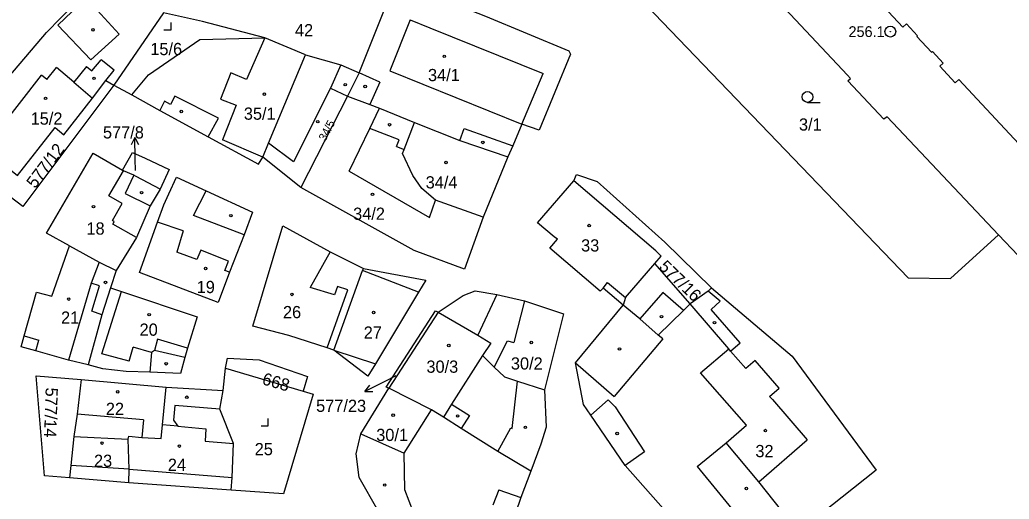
# Model space of a CAD drawing. Extents: x -758582 to -751794, y -998770 to -994350.
# Drawn here: x -754634.2 to -754496.6, y -996827 to -996760.3 of the extents above; entities that cross this region are included whole.
import ezdxf

# ---------------------------------------------------------------- set-up
doc = ezdxf.new("R2010")
doc.units = 0
for name, color, linetype in [('Hranice parcel', 7, 'Continuous'), ('Parcelní čísla', 7, 'Continuous'), ('Pop  PČ popisy', 7, 'Continuous'), ('Vnitřní kresba', 7, 'Continuous'), ('Značky bodu BP', 7, 'Continuous'), ('Značky budov', 7, 'Continuous'), ('Značky kultur', 7, 'Continuous')]:
    doc.layers.add(name, color=color, linetype=linetype)

msp = doc.modelspace()

# ---------------------------------------------------------------- linework, layer by layer
at = {"layer": 'Hranice parcel'}
for p, q in [((-754586.97, -996767.66), (-754583, -996757.68)), ((-754630.49, -996762.03), (-754626.47, -996757.97)), ((-754614.18, -996759.28), (-754621.09, -996769.34)), ((-754642.14, -996775.76), (-754630.49, -996762.03)), ((-754594.45, -996765.16), (-754600.1, -996762.77)), ((-754586.97, -996767.66), (-754588.61, -996770.89)), ((-754621.09, -996769.34), (-754618.62, -996770.71)), ((-754618.62, -996770.71), (-754614.71, -996772.89)), ((-754588.61, -996770.89), (-754595.09, -996783.62)), ((-754595.09, -996783.62), (-754600.38, -996779.37)), ((-754566.31, -996779.33), (-754569.76, -996787.73)), ((-754495.35, -996793.06), (-754498.09, -996790.19)), ((-754620.77, -996795.17), (-754621.55, -996797.57)), ((-754576.01, -996800.97), (-754582.85, -996811.54)), ((-754605.91, -996811.83), (-754605.57, -996808.76)), ((-754605.57, -996808.76), (-754594.79, -996811.96)), ((-754625.65, -996810.32), (-754613.81, -996811.37)), ((-754613.81, -996811.37), (-754605.91, -996811.83)), ((-754594.79, -996811.96), (-754593.39, -996812.37)), ((-754626.65, -996818.24), (-754619.11, -996818.64)), ((-754619.04, -996824.72), (-754627.29, -996824.01)), ((-754604.8, -996825.7), (-754619.04, -996824.72))]:
    msp.add_line(p, q, dxfattribs=at)
for points in [[(-754517.71, -996734.79), (-754521.88, -996738.79), (-754520.85, -996739.93), (-754523.11, -996742.06), (-754524.18, -996740.92), (-754527.46, -996744.01), (-754511.37, -996761.27), (-754510.88, -996760.84), (-754509.34, -996762.49), (-754509.43, -996762.58), (-754507.38, -996764.77), (-754507.28, -996764.69), (-754505.78, -996766.3), (-754506.25, -996766.72), (-754504.11, -996769.04), (-754503.6, -996768.55), (-754490.16, -996782.99), (-754490.7, -996783.49), (-754488.08, -996786.29), (-754495.35, -996793.06)], [(-754498.09, -996790.19), (-754513.58, -996773.76), (-754514.01, -996774.11), (-754519.03, -996768.77), (-754518.65, -996768.41), (-754519.06, -996767.99), (-754542.19, -996743.28)], [(-754550.52, -996754.59), (-754510.63, -996796.17), (-754504.74, -996796.25), (-754498.09, -996790.19)], [(-754576.26, -996757.01), (-754569.4, -996759.74), (-754557.83, -996764.59), (-754557.59, -996765.06), (-754561.98, -996775.61), (-754564.36, -996774.79), (-754565.63, -996777.81), (-754566.31, -996779.33)], [(-754600.1, -996762.77), (-754608.76, -996760.51), (-754614.18, -996759.28)], [(-754618.62, -996770.71), (-754616.29, -996767.9), (-754609.14, -996762.99), (-754600.1, -996762.77)], [(-754600.38, -996779.37), (-754599.61, -996777.41), (-754594.45, -996765.16)], [(-754594.45, -996765.16), (-754589.54, -996766.52), (-754586.97, -996767.66)], [(-754638.51, -996778.73), (-754634.52, -996781.92), (-754629.25, -996775.27), (-754628.08, -996776.26), (-754624.09, -996771.15), (-754622.2, -996768.72), (-754621.09, -996769.34)], [(-754621.09, -996769.34), (-754633.76, -996786.26), (-754640.43, -996781.18), (-754638.51, -996778.73)], [(-754588.61, -996770.89), (-754585.5, -996772.06), (-754584.18, -996772.56), (-754579.3, -996774.56)], [(-754614.71, -996772.89), (-754607.97, -996776.56), (-754601, -996780.37), (-754600.38, -996779.37)], [(-754569.76, -996787.73), (-754576.38, -996785.36), (-754578.28, -996783.73), (-754579.54, -996781.91), (-754580.96, -996778.85), (-754580.74, -996778.31), (-754579.3, -996774.56)], [(-754579.3, -996774.56), (-754572.98, -996777.04), (-754566.31, -996779.33)], [(-754627.28, -996791.74), (-754630.45, -996789.97), (-754623.98, -996778.83), (-754619.92, -996781.17)], [(-754619.92, -996781.17), (-754618.52, -996778.75), (-754616.77, -996779.54), (-754613.42, -996781.11), (-754614.68, -996783.82)], [(-754614.68, -996783.82), (-754618.01, -996782.06), (-754618.31, -996781.9), (-754619.77, -996781.26), (-754619.92, -996781.17)], [(-754617.55, -996795.43), (-754615.04, -996788.43), (-754614.17, -996786), (-754613.46, -996784.47), (-754612.4, -996782.17), (-754608.29, -996784.05), (-754601.81, -996787.05), (-754602.99, -996790.2), (-754605.02, -996795.38), (-754606.62, -996799.61), (-754617.55, -996795.43)], [(-754550.29, -996799.98), (-754553.08, -996797.59), (-754553.47, -996798.05), (-754560.48, -996792.05), (-754559.41, -996790.8), (-754559.89, -996790.48), (-754562.17, -996788.53), (-754557.12, -996782.67)], [(-754557.12, -996782.67), (-754556.79, -996781.79), (-754553.88, -996782.77), (-754544.49, -996791.21), (-754537.99, -996797.55)], [(-754540.94, -996799.81), (-754545.86, -996794.18), (-754544.98, -996793.17), (-754545.72, -996792.4), (-754557.12, -996782.67)], [(-754614.68, -996783.82), (-754616.04, -996786.16), (-754617.97, -996790.55), (-754620.77, -996795.17)], [(-754569.76, -996787.73), (-754572.33, -996794.98), (-754579.34, -996792.35), (-754595.09, -996783.62)], [(-754590.53, -996806.24), (-754591.46, -996805.92), (-754596.78, -996804.2), (-754601.77, -996802.92), (-754597.6, -996788.95), (-754591.03, -996792.57), (-754586.41, -996794.87)], [(-754624.7, -996808.3), (-754627.42, -996807.61), (-754631.95, -996806.33), (-754634, -996805.77), (-754633.58, -996804.24), (-754631.86, -996798.17), (-754629.75, -996798.74), (-754627.28, -996791.74)], [(-754627.28, -996791.74), (-754623.15, -996793.98), (-754620.77, -996795.17)], [(-754586.41, -996794.87), (-754577.73, -996796.52), (-754578.74, -996798.19), (-754584.74, -996808.14), (-754585.77, -996809.85), (-754590.53, -996806.24)], [(-754590.53, -996806.24), (-754586.53, -996795.15), (-754586.41, -996794.87)], [(-754621.55, -996797.57), (-754620.04, -996798.07), (-754609.54, -996801.58), (-754610.86, -996805.95), (-754611.22, -996807.27), (-754611.84, -996809.48), (-754616.11, -996809.31), (-754619.38, -996809.21), (-754622.65, -996808.83), (-754624.7, -996808.3)], [(-754621.55, -996797.57), (-754622.76, -996801.3), (-754624.7, -996808.3)], [(-754537.99, -996797.55), (-754538.47, -996798.02), (-754540.94, -996799.81)], [(-754537.99, -996797.55), (-754526.76, -996807.06), (-754515.08, -996822.93), (-754525.88, -996831.52)], [(-754576.01, -996800.97), (-754572.55, -996798.64), (-754570.84, -996797.96), (-754567.83, -996798.5)], [(-754567.83, -996798.5), (-754570.47, -996804.13), (-754568.7, -996805.26), (-754569.84, -996806.98), (-754568.21, -996808.6), (-754566.8, -996809.97), (-754564.95, -996810.55), (-754561.2, -996811.74)], [(-754567.83, -996798.5), (-754564.02, -996799.39), (-754558.56, -996801.18), (-754561.2, -996811.74)], [(-754525.88, -996831.52), (-754529.97, -996834.72), (-754530.8, -996833.6), (-754535.24, -996836.36), (-754537.32, -996836.16), (-754539.06, -996834.69), (-754550.01, -996822.3), (-754554.77, -996815.29), (-754555.79, -996813.82), (-754556.89, -996808.01), (-754550.29, -996799.98)], [(-754540.94, -996799.81), (-754541.88, -996800.73), (-754545.4, -996804.17), (-754547.97, -996801.87), (-754550.29, -996799.98)], [(-754525.88, -996831.52), (-754531.43, -996824.54), (-754535.95, -996819.14), (-754533.11, -996816.66), (-754539.52, -996809.39), (-754535.59, -996806.07), (-754540.94, -996799.81)], [(-754582.85, -996811.54), (-754583.23, -996811.38), (-754576.38, -996800.76), (-754576.01, -996800.97)], [(-754605.57, -996808.76), (-754605.32, -996807.35), (-754600.92, -996807.59), (-754594.19, -996809.9), (-754594.79, -996811.96)], [(-754627.29, -996824.01), (-754630.74, -996823.71), (-754631.93, -996809.82), (-754625.65, -996810.32)], [(-754625.65, -996810.32), (-754626.22, -996815.14), (-754626.65, -996818.24)], [(-754619.11, -996818.64), (-754619.03, -996818.22), (-754617.21, -996818.41), (-754614.52, -996818.55), (-754614.33, -996816.61), (-754613.81, -996811.37)], [(-754563.13, -996823.1), (-754564.53, -996826.74), (-754565.27, -996828.9), (-754569.1, -996839.07), (-754577.26, -996836.37), (-754579.33, -996834.34), (-754581.37, -996832.02), (-754584.33, -996828.61), (-754587, -996823.94), (-754587.4, -996820.67), (-754586.75, -996817.88), (-754582.85, -996811.54)], [(-754563.13, -996823.1), (-754567.7, -996820.33), (-754572.79, -996817.13), (-754575.28, -996815.57), (-754576.94, -996814.54), (-754582.85, -996811.54)], [(-754604.8, -996825.7), (-754604.63, -996823.94), (-754604.49, -996819.21), (-754606.35, -996814.45), (-754605.91, -996811.83)], [(-754593.39, -996812.37), (-754597.52, -996826.21), (-754604.8, -996825.7)], [(-754561.2, -996811.74), (-754560.98, -996816.97), (-754561.71, -996819.34), (-754563.13, -996823.1)], [(-754626.65, -996818.24), (-754627.08, -996822.31), (-754627.29, -996824.01)], [(-754619.04, -996824.72), (-754618.99, -996822.78), (-754619.11, -996818.64)]]:
    msp.add_lwpolyline(points, dxfattribs=at)
at = {"layer": 'Pop  PČ popisy'}
for p, q in [((-754618.19, -996776.65), (-754618.68, -996777.66)), ((-754618.14, -996779.65), (-754618.19, -996776.65)), ((-754618.19, -996776.65), (-754617.67, -996777.64)), ((-754618.11, -996781.23), (-754618.14, -996779.65)), ((-754581.9, -996809.79), (-754583.52, -996810.64)), ((-754583.52, -996810.64), (-754586.19, -996812)), ((-754586.19, -996812), (-754585.53, -996811.1)), ((-754586.19, -996812), (-754585.07, -996811.99))]:
    msp.add_line(p, q, dxfattribs=at)
at = {"layer": 'Vnitřní kresba'}
for p, q in [((-754624.94, -996757.21), (-754628.9, -996760.99)), ((-754620.36, -996762.25), (-754624.94, -996757.21)), ((-754579.88, -996760.26), (-754582.71, -996767.35)), ((-754579.88, -996760.26), (-754577.15, -996761.36)), ((-754624.3, -996765.83), (-754628.9, -996760.99)), ((-754577.15, -996761.36), (-754561.42, -996767.72)), ((-754624.3, -996765.83), (-754620.36, -996762.25)), ((-754600.1, -996762.77), (-754602.68, -996768.58)), ((-754624.15, -996767.37), (-754622.87, -996765.85)), ((-754621.06, -996767.26), (-754622.87, -996765.85)), ((-754630.43, -996768.56), (-754629.08, -996766.88)), ((-754626.65, -996768.96), (-754629.08, -996766.88)), ((-754624.92, -996766.76), (-754626.65, -996768.96)), ((-754624.92, -996766.76), (-754624.15, -996767.37)), ((-754622.2, -996768.72), (-754621.06, -996767.26)), ((-754589.54, -996766.52), (-754590.96, -996769.76)), ((-754582.71, -996767.35), (-754564.36, -996774.79)), ((-754639.16, -996778.21), (-754631.17, -996767.99)), ((-754630.43, -996768.56), (-754631.17, -996767.99)), ((-754604.83, -996767.64), (-754606.27, -996771.29)), ((-754602.68, -996768.58), (-754604.83, -996767.64)), ((-754584.13, -996768.92), (-754586.97, -996767.66)), ((-754584.13, -996768.92), (-754585.5, -996772.06)), ((-754564.36, -996774.79), (-754561.42, -996767.72)), ((-754626.65, -996768.96), (-754624.09, -996771.15)), ((-754590.96, -996769.76), (-754596.12, -996780.02)), ((-754590.96, -996769.76), (-754588.61, -996770.89)), ((-754614.07, -996771.6), (-754614.71, -996772.89)), ((-754613.21, -996772.03), (-754614.07, -996771.6)), ((-754612.62, -996770.88), (-754613.21, -996772.03)), ((-754606.56, -996773.97), (-754612.62, -996770.88)), ((-754606.27, -996771.29), (-754604.09, -996772.16)), ((-754604.09, -996772.16), (-754606, -996776.99)), ((-754585.53, -996775.41), (-754584.18, -996772.56)), ((-754607.97, -996776.56), (-754606.56, -996773.97)), ((-754588.39, -996781.31), (-754585.53, -996775.41)), ((-754581.41, -996776.96), (-754585.53, -996775.41)), ((-754572.98, -996777.04), (-754572.4, -996775.37)), ((-754572.4, -996775.37), (-754565.63, -996777.81)), ((-754600.38, -996779.37), (-754606, -996776.99)), ((-754581.8, -996777.91), (-754581.41, -996776.96)), ((-754596.12, -996780.02), (-754599.61, -996777.41)), ((-754581.8, -996777.91), (-754580.74, -996778.31)), ((-754621.8, -996784.78), (-754619.77, -996781.26)), ((-754618.31, -996781.9), (-754619.52, -996784.43)), ((-754588.39, -996781.31), (-754577.21, -996787.77)), ((-754610.05, -996787.48), (-754608.29, -996784.05)), ((-754619.96, -996785.83), (-754621.8, -996784.78)), ((-754619.52, -996784.43), (-754616.04, -996786.16)), ((-754577.21, -996787.77), (-754576.38, -996785.36)), ((-754621.3, -996788.2), (-754619.96, -996785.83)), ((-754602.99, -996790.2), (-754610.05, -996787.48)), ((-754621.05, -996788.36), (-754621.3, -996788.2)), ((-754621.25, -996788.7), (-754621.05, -996788.36)), ((-754617.97, -996790.55), (-754621.25, -996788.7)), ((-754611.47, -996789.63), (-754615.04, -996788.43)), ((-754611.47, -996789.63), (-754612.37, -996792.58)), ((-754609.55, -996793.63), (-754612.37, -996792.58)), ((-754609.03, -996792.33), (-754609.55, -996793.63)), ((-754605.15, -996793.85), (-754609.03, -996792.33)), ((-754591.03, -996792.57), (-754593.79, -996797.52)), ((-754623.15, -996793.98), (-754624.27, -996796.93)), ((-754605.65, -996795.14), (-754605.15, -996793.85)), ((-754549.96, -996798.92), (-754545.86, -996794.18)), ((-754605.02, -996795.38), (-754605.65, -996795.14)), ((-754578.74, -996798.19), (-754586.53, -996795.15)), ((-754624.27, -996796.93), (-754627.42, -996807.61)), ((-754623.12, -996797.27), (-754624.27, -996796.93)), ((-754624.18, -996800.81), (-754623.12, -996797.27)), ((-754590.41, -996798.55), (-754593.79, -996797.52)), ((-754590.02, -996797.39), (-754590.41, -996798.55)), ((-754588.58, -996797.86), (-754590.02, -996797.39)), ((-754553.08, -996797.59), (-754552.45, -996796.82)), ((-754552.45, -996796.82), (-754549.96, -996798.92)), ((-754622.8, -996806.73), (-754620.04, -996798.07)), ((-754591.46, -996805.92), (-754588.58, -996797.86)), ((-754549.96, -996798.92), (-754550.29, -996799.98)), ((-754544.76, -996798.2), (-754547.97, -996801.87)), ((-754541.88, -996800.73), (-754544.76, -996798.2)), ((-754536.8, -996799.42), (-754538.47, -996798.02)), ((-754564.02, -996799.39), (-754565.47, -996805.16)), ((-754538.05, -996800.56), (-754536.8, -996799.42)), ((-754534.01, -996805.21), (-754538.05, -996800.56)), ((-754622.76, -996801.3), (-754624.18, -996800.81)), ((-754576.01, -996800.97), (-754570.47, -996804.13)), ((-754633.58, -996804.24), (-754631.54, -996804.85)), ((-754544.74, -996804.67), (-754551.52, -996812.7)), ((-754544.74, -996804.67), (-754545.4, -996804.17)), ((-754631.95, -996806.33), (-754631.54, -996804.85)), ((-754618.97, -996807.76), (-754618.43, -996805.84)), ((-754615.88, -996806.55), (-754618.43, -996805.84)), ((-754615.02, -996804.72), (-754615.44, -996806.3)), ((-754610.86, -996805.95), (-754615.02, -996804.72)), ((-754568.21, -996808.6), (-754566.35, -996804.92)), ((-754566.35, -996804.92), (-754565.47, -996805.16)), ((-754535.33, -996806.37), (-754535.59, -996806.07)), ((-754535.33, -996806.37), (-754534.01, -996805.21)), ((-754618.97, -996807.76), (-754622.8, -996806.73)), ((-754615.88, -996806.55), (-754616.11, -996809.31)), ((-754615.44, -996806.3), (-754615.88, -996806.55)), ((-754611.22, -996807.27), (-754615.44, -996806.3)), ((-754590.53, -996806.24), (-754584.74, -996808.14)), ((-754569.84, -996806.98), (-754574.14, -996813.77)), ((-754533.2, -996808.8), (-754535.33, -996806.37)), ((-754556.89, -996808.01), (-754551.52, -996812.7)), ((-754531.91, -996807.69), (-754533.2, -996808.8)), ((-754528.58, -996811.52), (-754531.91, -996807.69)), ((-754565.7, -996817.16), (-754564.95, -996810.55)), ((-754529.91, -996812.67), (-754528.58, -996811.52)), ((-754529.49, -996813.12), (-754529.91, -996812.67)), ((-754612.61, -996813.94), (-754612.8, -996815.97)), ((-754606.35, -996814.45), (-754612.61, -996813.94)), ((-754574.14, -996813.77), (-754575.28, -996815.57)), ((-754574.14, -996813.77), (-754571.64, -996815.31)), ((-754552.35, -996813.15), (-754554.77, -996815.29)), ((-754551.38, -996814.13), (-754552.35, -996813.15)), ((-754551.38, -996814.13), (-754547.32, -996820.39)), ((-754529.49, -996813.12), (-754524.67, -996818.72)), ((-754616.98, -996815.94), (-754626.22, -996815.14)), ((-754580.71, -996820.56), (-754576.94, -996814.54)), ((-754571.64, -996815.31), (-754572.79, -996817.13)), ((-754616.98, -996815.94), (-754617.21, -996818.41)), ((-754612.22, -996816.81), (-754614.33, -996816.61)), ((-754612.8, -996815.97), (-754612.22, -996816.81)), ((-754612.22, -996816.81), (-754608.33, -996817.18)), ((-754567.7, -996820.33), (-754565.91, -996817.05)), ((-754565.91, -996817.05), (-754565.7, -996817.16)), ((-754608.33, -996817.18), (-754608.43, -996818.89)), ((-754586.75, -996817.88), (-754580.71, -996820.56)), ((-754608.43, -996818.89), (-754604.49, -996819.21)), ((-754540, -996822.41), (-754535.95, -996819.14)), ((-754531.43, -996824.54), (-754524.67, -996818.72)), ((-754580.63, -996825.69), (-754580.71, -996820.56)), ((-754547.32, -996820.39), (-754550.01, -996822.3)), ((-754618.99, -996822.78), (-754627.08, -996822.31)), ((-754540, -996822.41), (-754530.8, -996833.6)), ((-754618.99, -996822.78), (-754604.63, -996823.94)), ((-754579.43, -996828.85), (-754580.63, -996825.69)), ((-754567.56, -996825.66), (-754568.38, -996827.8)), ((-754567.56, -996825.66), (-754564.53, -996826.74))]:
    msp.add_line(p, q, dxfattribs=at)
at = {"layer": 'Značky bodu BP'}
for radius in [0.75, 0.03]:
    msp.add_circle((-754513.12, -996761.91), radius, dxfattribs=at)
at = {"layer": 'Značky budov'}
for centre in [(-754624.01, -996761.66), (-754575.15, -996765.35), (-754623.86, -996768.4), (-754588.93, -996769.29), (-754586.15, -996769.54), (-754630.6, -996771.19), (-754600.17, -996770.61), (-754611.73, -996773.02), (-754592.75, -996774.43), (-754582.76, -996774.87), (-754569.8, -996777.33), (-754574.91, -996780.12), (-754617.25, -996784.33), (-754585.14, -996784.55), (-754623.93, -996786.26), (-754604.83, -996787.53), (-754555, -996788.9), (-754608.34, -996794.88), (-754622.27, -996796.81), (-754627.38, -996799.13), (-754596.34, -996798.48), (-754616.19, -996801.29), (-754584.98, -996801), (-754544.95, -996801.57), (-754537.57, -996802.41), (-754574.53, -996805.59), (-754563.05, -996805.17), (-754550.78, -996806.07), (-754613.83, -996808.13), (-754620.57, -996812.04), (-754610.95, -996812.79), (-754582.27, -996815.29), (-754573.3, -996815.39), (-754563.88, -996816.98), (-754551.12, -996817.84), (-754530.5, -996817.43), (-754622.75, -996819.17), (-754611.99, -996819.59), (-754583.44, -996825.01), (-754533.14, -996825.49)]:
    msp.add_circle(centre, 0.175, dxfattribs=at)
at = {"layer": 'Značky kultur'}
for p, q in [((-754613.14, -996761.66), (-754613.14, -996760.66)), ((-754614.14, -996761.66), (-754613.14, -996761.66)), ((-754524.64, -996771.75), (-754522.89, -996771.75)), ((-754600.64, -996816.77), (-754599.64, -996816.77)), ((-754599.64, -996816.77), (-754599.64, -996815.77))]:
    msp.add_line(p, q, dxfattribs=at)
msp.add_circle((-754524.64, -996771), 0.75, dxfattribs=at)

# ---------------------------------------------------------------- texts
at = {"layer": 'Parcelní čísla'}
for s, p in [('42', (-754595.92, -996762.56)), ('15/6', (-754616.04, -996765.18)), ('34/1', (-754577.42, -996768.8)), ('35/1', (-754603.03, -996774.17)), ('15/2', (-754632.68, -996774.86)), ('3/1', (-754525.83, -996775.68)), ('577/8', (-754622.62, -996776.78)), ('34/4', (-754577.74, -996783.73)), ('34/2', (-754587.83, -996788.1)), ('18', (-754624.92, -996790.16)), ('33', (-754556.13, -996792.51)), ('19', (-754609.59, -996798.3)), ('26', (-754597.59, -996801.79)), ('21', (-754628.45, -996802.55)), ('20', (-754617.53, -996804.23)), ('27', (-754586.36, -996804.64)), ('30/2', (-754565.89, -996808.94)), ('30/3', (-754577.64, -996809.38)), ('22', (-754622.22, -996815.25)), ('577/23', (-754592.98, -996814.83)), ('30/1', (-754584.62, -996818.88)), ('25', (-754601.52, -996820.86)), ('32', (-754531.89, -996821.13)), ('23', (-754623.87, -996822.48)), ('24', (-754613.6, -996823.04))]:
    msp.add_text(s, height=1.7, dxfattribs=at).set_placement(p)
for s, height, rotation, p in [('34/5', 1.139, 62, (-754591.69, -996777.23)), ('577/12', 1.7, 53, (-754632.05, -996783.84)), ('577/16', 1.7, 316, (-754545.43, -996794.78)), ('668', 1.7, 344, (-754600.6, -996810.96)), ('577/14', 1.7, 268, (-754630.58, -996811.42))]:
    msp.add_text(s, height=height, rotation=rotation, dxfattribs=at).set_placement(p)
at = {"layer": 'Značky bodu BP'}
msp.add_text('256.1', height=1.5, dxfattribs=at).set_placement((-754518.94, -996762.66))

doc.saveas('drawing.dxf')
